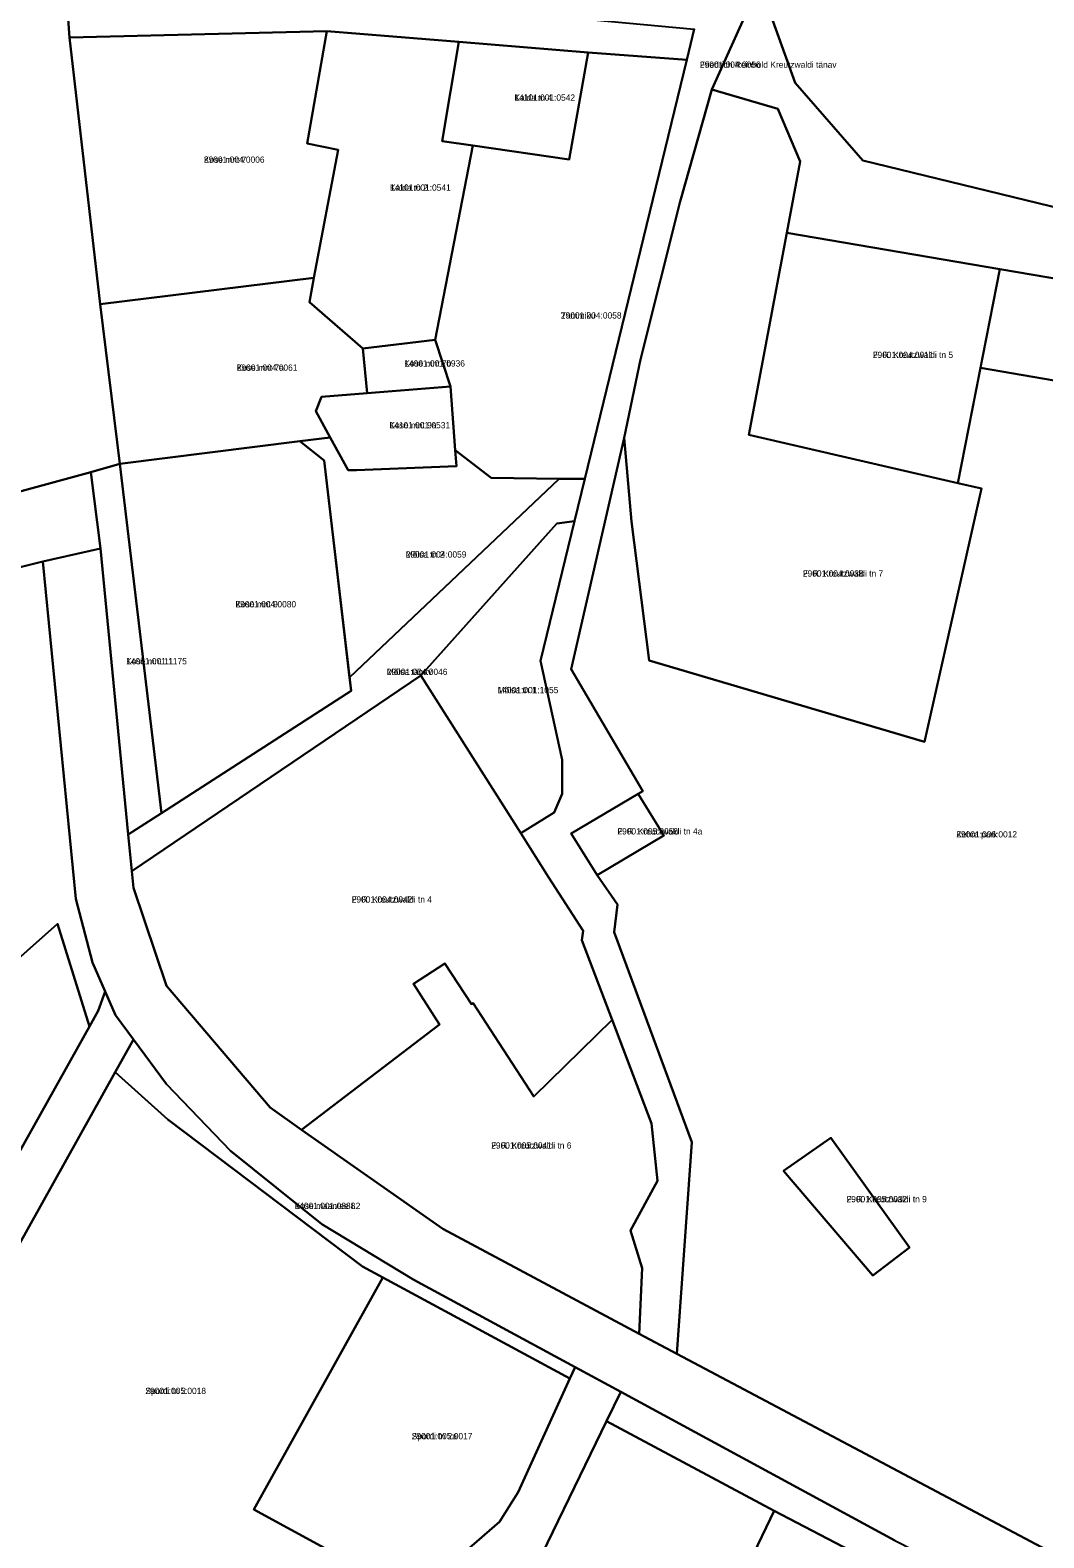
# Model space of a CAD drawing. Extents: x 566437 to 602312, y 6556921 to 6586574.
# Drawn here: x 575830.2 to 576072.4, y 6577820.6 to 6578180.7 of the extents above; entities that cross this region are included whole.
import ezdxf

# ---------------------------------------------------------------- set-up
doc = ezdxf.new("R2010")
doc.units = 0
for name, color, linetype in [('L_AADRESS', 7, 'Continuous'), ('PIIR', 7, 'Continuous'), ('TUNNUS', 7, 'Continuous')]:
    doc.layers.add(name, color=color, linetype=linetype)

msp = doc.modelspace()

# ---------------------------------------------------------------- linework, layer by layer
at = {"layer": 'PIIR'}
for points in [[(576033.48, 6578244.69), (576039.35, 6578245.45), (576103.79, 6578253.77), (576116.1, 6578233.77), (576107.54, 6578199.66), (576095.94, 6578142.53), (576095.84, 6578138.38), (576098.34, 6578135.57), (576094.95, 6578133.52), (576029.14, 6578149.52), (576012.98, 6578168.14), (576004.48, 6578191.82), (576018.47, 6578246.18), (576026.93, 6578245.34)], [(575837.5, 6578207.41), (575904.4, 6578192.82), (575948.44, 6578184.66), (575988.86, 6578180.95), (575987.07, 6578173.61), (575963.53, 6578175.39), (575932.63, 6578177.87), (575901.06, 6578180.43), (575839.56, 6578178.91)], [(575901.06, 6578180.43), (575896.37, 6578153.62), (575903.77, 6578152.13), (575897.96, 6578121.55), (575846.88, 6578115.27), (575839.56, 6578178.91)], [(575896.37, 6578153.62), (575901.06, 6578180.43), (575932.63, 6578177.87), (575928.65, 6578154.15), (575935.93, 6578153.1), (575926.9, 6578106.72), (575909.68, 6578104.68), (575896.92, 6578115.68), (575897.96, 6578121.55), (575903.77, 6578152.13)], [(575928.65, 6578154.15), (575932.63, 6578177.87), (575963.53, 6578175.39), (575958.96, 6578149.79), (575935.93, 6578153.1)], [(575963.53, 6578175.39), (575987.07, 6578173.61), (575962.71, 6578073.52), (575956.54, 6578073.52), (575940.33, 6578073.78), (575931.71, 6578080.33), (575930.58, 6578095.56), (575926.9, 6578106.72), (575935.93, 6578153.1), (575958.96, 6578149.79)], [(575993.05, 6578166.55), (576008.82, 6578161.9), (576014.15, 6578149.34), (576010.95, 6578132.25), (576001.92, 6578084.01), (576051.81, 6578072.52), (576057.53, 6578071.2), (576043.91, 6578010.67), (575978.11, 6578030.12), (575973.87, 6578063.29), (575972.1, 6578083.32), (575976.04, 6578101.99), (575985.47, 6578139.77)], [(576061.88, 6578123.57), (576051.81, 6578072.52), (576001.92, 6578084.01), (576010.95, 6578132.25)], [(576057.23, 6578100.02), (576061.88, 6578123.57), (576084.85, 6578119.66), (576094.76, 6578110.22), (576082.31, 6578095.74)], [(575846.88, 6578115.27), (575897.96, 6578121.55), (575896.92, 6578115.68), (575909.68, 6578104.68), (575910.69, 6578093.97), (575899.79, 6578093.1), (575898.46, 6578089.71), (575901.87, 6578083.4), (575894.63, 6578082.5), (575851.6, 6578077.1)], [(575926.9, 6578106.72), (575930.58, 6578095.56), (575910.69, 6578093.97), (575909.68, 6578104.68)], [(575898.46, 6578089.71), (575899.79, 6578093.1), (575910.69, 6578093.97), (575930.58, 6578095.56), (575931.71, 6578080.33), (575932.04, 6578076.57), (575908.12, 6578075.61), (575906.11, 6578075.58), (575901.87, 6578083.4)], [(575894.63, 6578082.5), (575901.87, 6578083.4), (575906.11, 6578075.58), (575908.12, 6578075.61), (575932.04, 6578076.57), (575931.71, 6578080.33), (575940.33, 6578073.78), (575956.54, 6578073.52), (575906.46, 6578026.03), (575900.42, 6578077.86)], [(575894.63, 6578082.5), (575900.42, 6578077.86), (575906.83, 6578022.87), (575861.56, 6577993.7), (575851.6, 6578077.07)], [(575861.56, 6577993.7), (575853.61, 6577988.58), (575846.93, 6578056.87), (575844.63, 6578075.15), (575851.6, 6578077.07)], [(575962.71, 6578073.52), (575960.24, 6578063.39), (575956.03, 6578062.82), (575923.5, 6578026.55), (575854.47, 6577979.82), (575853.61, 6577988.58), (575861.56, 6577993.7), (575906.83, 6578022.87), (575906.46, 6578026.03), (575956.54, 6578073.52)], [(575955.36, 6577993.85), (575947.41, 6577988.89), (575923.5, 6578026.55), (575956.03, 6578062.82), (575960.24, 6578063.39), (575952.13, 6578030.07), (575957.27, 6578006.41), (575957.27, 6577998.27)], [(575923.5, 6578026.55), (575947.41, 6577988.89), (575954.06, 6577978.34), (575962.29, 6577965.58), (575962.01, 6577963.34), (575969.23, 6577944.26), (575950.49, 6577926.01), (575936.01, 6577948.29), (575935.65, 6577948.05), (575929.27, 6577957.78), (575921.79, 6577952.88), (575928, 6577943.16), (575894.98, 6577918.06), (575887.48, 6577923.32), (575862.77, 6577952.43), (575854.86, 6577975.83), (575854.47, 6577979.82)], [(575975.44, 6577998.27), (575981.56, 6577988.32), (575965.62, 6577978.86), (575959.43, 6577988.78)], [(575744.53, 6577885.26), (575836.67, 6577967.26), (575844.34, 6577942.69), (575795.58, 6577855.72)], [(575975.72, 6577869.31), (575928.74, 6577894.37), (575894.98, 6577918.06), (575928, 6577943.16), (575921.79, 6577952.88), (575929.27, 6577957.78), (575935.65, 6577948.05), (575936.01, 6577948.29), (575950.49, 6577926.01), (575969.23, 6577944.26), (575978.6, 6577919.52), (575980.07, 6577905.81), (575973.6, 6577894), (575976.41, 6577885)], [(575848.09, 6577951.09), (575850.57, 6577945.38), (575854.84, 6577939.62), (575850.46, 6577931.78), (575803.49, 6577847.64), (575796.08, 6577832.19), (575793.56, 6577826.93), (575783.37, 6577800.79), (575782.51, 6577784.1), (575786.23, 6577773.43), (575774.21, 6577790.58), (575761.81, 6577796.47), (575770.83, 6577801.08), (575778.59, 6577822.18), (575795.58, 6577855.72), (575844.34, 6577942.69), (575846.38, 6577946.48)], [(575960.37, 6577861.34), (575959.12, 6577858.6), (575914.42, 6577882.76), (575909.54, 6577885.39), (575863.06, 6577920.52), (575850.46, 6577931.78), (575854.84, 6577939.62), (575862.75, 6577928.96), (575878, 6577912.97), (575899.87, 6577895.47), (575921.81, 6577882.2)], [(575850.46, 6577931.78), (575863.06, 6577920.52), (575909.54, 6577885.39), (575914.42, 6577882.76), (575883.57, 6577827.35), (575919.29, 6577807.9), (575871.03, 6577777.08), (575830.84, 6577799.41), (575836.57, 6577809.77), (575796.08, 6577832.19), (575803.49, 6577847.64)], [(576010.18, 6577908.23), (576031.51, 6577883.19), (576040.32, 6577889.95), (576021.52, 6577916.08)], [(576010.18, 6577908.23), (576021.52, 6577916.08), (576040.32, 6577889.95), (576031.51, 6577883.19)], [(575914.42, 6577882.76), (575959.12, 6577858.6), (575946.76, 6577831.44), (575942.32, 6577824.42), (575934.48, 6577817.6), (575919.29, 6577807.9), (575883.57, 6577827.35)], [(575799.52, 6577754.47), (575818.69, 6577743.86), (575867.62, 6577774.9), (575871.03, 6577777.08), (575919.29, 6577807.9), (575934.48, 6577817.6), (575942.32, 6577824.42), (575946.76, 6577831.44), (575959.12, 6577858.6), (575960.37, 6577861.34), (575971.27, 6577855.43), (575967.88, 6577848.45), (575947.38, 6577806.27), (575968.21, 6577790.58), (575965.45, 6577786.8), (575937.06, 6577803.56), (575897.69, 6577779.77), (575851.77, 6577751.73), (575852.31, 6577750.92), (575822.08, 6577730.9), (575821.05, 6577726.98)], [(576111.82, 6577780.55), (576106.96, 6577774.73), (576066.11, 6577796.68), (576007.96, 6577827.04), (575967.88, 6577848.45), (575971.27, 6577855.43), (576036.81, 6577819.97), (576088.98, 6577793.42)], [(575967.88, 6577848.45), (576007.96, 6577827.04), (576002.1, 6577814.93), (576006.75, 6577803.99), (576000.38, 6577791.22), (575982.13, 6577780.1), (575968.21, 6577790.58), (575947.38, 6577806.27)], [(576066.11, 6577796.68), (576049.23, 6577769.36), (576000.38, 6577791.22), (576006.75, 6577803.99), (576002.1, 6577814.93), (576007.96, 6577827.04)]]:
    msp.add_lwpolyline(points, close=True, dxfattribs=at)
for points in [[(575837.5, 6578207.41), (575839.56, 6578178.91), (575846.88, 6578115.27), (575851.6, 6578077.1), (575844.63, 6578075.15), (575827.14, 6578070.34), (575821.58, 6578118.28), (575813.75, 6578179.27), (575808.57, 6578223.68)], [(576004.48, 6578191.82), (575993.05, 6578166.55), (575985.47, 6578139.77), (575976.04, 6578101.99), (575972.1, 6578083.32), (575959.46, 6578028.07), (575976.59, 6577998.93), (575975.44, 6577998.27), (575959.43, 6577988.78), (575965.62, 6577978.86), (575970.54, 6577971.81), (575969.7, 6577965.2), (575988.3, 6577915.11), (575984.71, 6577864.52), (575975.72, 6577869.31), (575976.41, 6577885), (575973.6, 6577894), (575980.07, 6577905.81), (575978.6, 6577919.52), (575969.23, 6577944.26), (575962.01, 6577963.34), (575962.29, 6577965.58), (575954.06, 6577978.34), (575947.41, 6577988.89), (575955.36, 6577993.85), (575957.27, 6577998.27), (575957.27, 6578006.41), (575952.13, 6578030.07), (575960.24, 6578063.39), (575962.71, 6578073.52), (575987.07, 6578173.61), (575988.86, 6578180.95)], [(576084.85, 6578119.66), (576061.88, 6578123.57), (576010.95, 6578132.25), (576014.15, 6578149.34), (576008.82, 6578161.9), (575993.05, 6578166.55), (576004.48, 6578191.82), (576012.98, 6578168.14), (576029.14, 6578149.52), (576094.95, 6578133.52)], [(576095.59, 6577805.76), (575991.44, 6577860.93), (575984.71, 6577864.52), (575988.3, 6577915.11), (575969.7, 6577965.2), (575970.54, 6577971.81), (575965.62, 6577978.86), (575981.56, 6577988.32), (575975.44, 6577998.27), (575976.59, 6577998.93), (575959.46, 6578028.07), (575972.1, 6578083.32), (575973.87, 6578063.29), (575978.11, 6578030.12), (576043.91, 6578010.67), (576057.53, 6578071.2), (576051.81, 6578072.52), (576057.23, 6578100.02), (576082.31, 6578095.74)], [(575827.14, 6578070.34), (575844.63, 6578075.15), (575846.93, 6578056.87), (575833.16, 6578053.76), (575791.18, 6578043.37)], [(576036.81, 6577819.97), (575971.27, 6577855.43), (575960.37, 6577861.34), (575921.81, 6577882.2), (575899.87, 6577895.47), (575878, 6577912.97), (575862.75, 6577928.96), (575854.84, 6577939.62), (575850.57, 6577945.38), (575848.09, 6577951.09), (575845.06, 6577958.03), (575841.06, 6577973.23), (575833.16, 6578053.76), (575846.93, 6578056.87), (575853.61, 6577988.58), (575854.47, 6577979.82), (575854.86, 6577975.83), (575862.77, 6577952.43), (575887.48, 6577923.32), (575894.98, 6577918.06), (575928.74, 6577894.37), (575975.72, 6577869.31), (575984.71, 6577864.52), (575991.44, 6577860.93), (576095.59, 6577805.76)], [(575791.18, 6578043.37), (575833.16, 6578053.76), (575841.06, 6577973.23), (575845.06, 6577958.03), (575848.09, 6577951.09), (575846.38, 6577946.48), (575844.34, 6577942.69), (575836.67, 6577967.26), (575744.53, 6577885.26)]]:
    msp.add_lwpolyline(points, dxfattribs=at)

# ---------------------------------------------------------------- texts
at = {"layer": 'L_AADRESS'}
for s, p in [('Friedrich Reinhold Kreutzwaldi tänav', (575990.2, 6578171.7)), ('Kalda tn 4', (575945.87, 6578163.83)), ('Kose mnt 7', (575871.67, 6578149.01)), ('Kalda tn 2', (575916.15, 6578142.33)), ('Tammiku', (575956.98, 6578111.8)), ('Kose mnt 7b', (575919.55, 6578100.34)), ('F. R. Kreutzwaldi tn 5', (576031.53, 6578102.38)), ('Kose mnt 7a', (575879.52, 6578099.33)), ('Kose mnt 9a', (575916.01, 6578085.57)), ('Mõisa tn 2', (575919.91, 6578054.71)), ('F. R. Kreutzwaldi tn 7', (576014.82, 6578050.16)), ('Kose mnt 9', (575879.21, 6578042.82)), ('Kose mnt 11', (575853.1, 6578029.2)), ('Mõisa tänav', (575915.37, 6578026.67)), ('Mõisa tn 1', (575941.87, 6578022.32)), ('F. R. Kreutzwaldi tn 4a', (575970.49, 6577988.57)), ('Kehra park', (576051.49, 6577987.86)), ('F. R. Kreutzwaldi tn 4', (575907, 6577972.3)), ('F. R. Kreutzwaldi tn 6', (575940.33, 6577913.54)), ('Kose maantee L2', (575893.35, 6577899.11)), ('F. R. Kreutzwaldi tn 9', (576025.25, 6577900.72)), ('Spordi tn 2', (575857.68, 6577854.91)), ('Spordi tn 2a', (575921.34, 6577844.11))]:
    msp.add_text(s, height=1.5, dxfattribs=at).set_placement(p)
at = {"layer": 'TUNNUS'}
for s, p in [('29001:004:0056', (575990.2, 6578171.7)), ('14101:001:0542', (575945.87, 6578163.83)), ('29001:004:0006', (575871.67, 6578149.01)), ('14101:001:0541', (575916.15, 6578142.33)), ('29001:004:0058', (575956.98, 6578111.8)), ('14001:001:0936', (575919.55, 6578100.34)), ('29001:004:0011', (576031.53, 6578102.38)), ('29001:004:0061', (575879.52, 6578099.33)), ('14101:001:0531', (575916.01, 6578085.57)), ('29001:004:0059', (575919.91, 6578054.71)), ('29001:004:0038', (576014.82, 6578050.16)), ('29001:004:0080', (575879.21, 6578042.82)), ('14001:001:1175', (575853.1, 6578029.2)), ('29001:004:0046', (575915.37, 6578026.67)), ('14001:001:1055', (575941.87, 6578022.32)), ('29001:005:0056', (575970.49, 6577988.57)), ('29001:006:0012', (576051.49, 6577987.86)), ('29001:004:0042', (575907, 6577972.3)), ('29001:005:0041', (575940.33, 6577913.54)), ('14001:001:0888', (575893.35, 6577899.11)), ('29001:005:0032', (576025.25, 6577900.72)), ('29001:005:0018', (575857.68, 6577854.91)), ('29001:005:0017', (575921.34, 6577844.11))]:
    msp.add_text(s, height=1.5, dxfattribs=at).set_placement(p)

doc.saveas('drawing.dxf')
